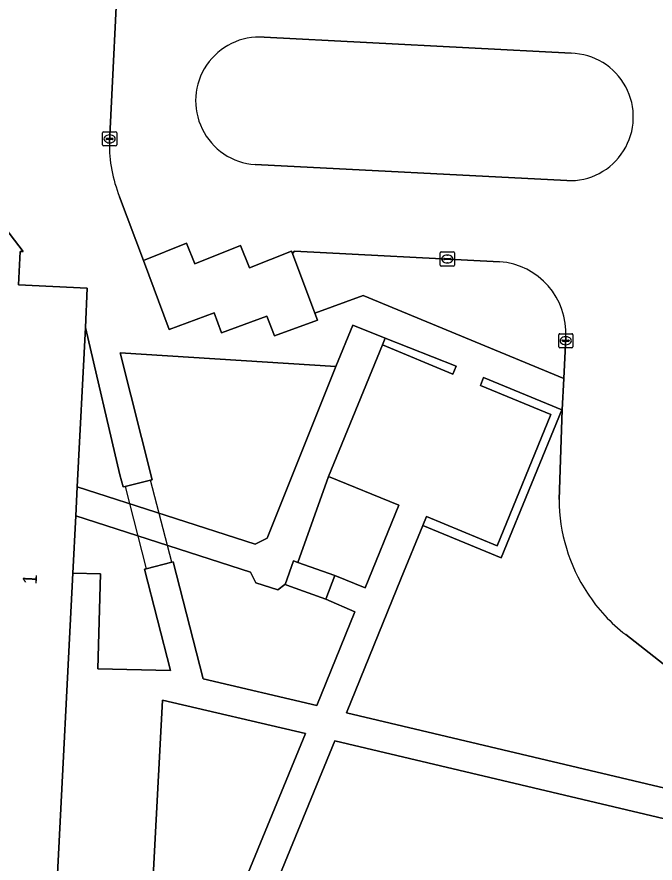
# Model space of a CAD drawing. Extents: x 161758 to 162722, y 384793 to 385405.
# Drawn here: x 161993.6 to 162038.8, y 385039.1 to 385099.1 of the extents above; entities that cross this region are included whole.
import ezdxf

# ---------------------------------------------------------------- set-up
doc = ezdxf.new("R2010")
doc.units = 0
for name, color, linetype in [('IMGEO_Berm_halfverhard', 7, 'Continuous'), ('IMGEO_Dek', 7, 'Continuous'), ('IMGEO_Erf', 7, 'Continuous'), ('IMGEO_Groenvoorziening', 7, 'Continuous'), ('IMGEO_Haag', 7, 'Continuous'), ('IMGEO_Kolk', 7, 'Continuous'), ('IMGEO_Muur', 7, 'Continuous'), ('IMGEO_Pand', 7, 'Continuous'), ('IMGEO_Pand_nummerreeks', 7, 'Continuous'), ('IMGEO_Parkeervlak_open', 7, 'Continuous'), ('IMGEO_Voetpad_op_trap', 7, 'Continuous'), ('IMGEO_Voetpad_open', 7, 'Continuous')]:
    doc.layers.add(name, color=color, linetype=linetype)

msp = doc.modelspace()

# ---------------------------------------------------------------- linework, layer by layer
at = {"layer": 'IMGEO_Berm_halfverhard'}
for points in [[(162032.226, 385071.255), (162032.207, 385071.263), (162027.911, 385060.765), (162022.337, 385063.052), (162020.819, 385059.326), (162016.934, 385049.788), (162056.758, 385040.344), (162056.822, 385040.582)], [(162031.999, 385064.905), (162032.226, 385071.255)], [(162051.708, 385043.574), (162043.338, 385050.139), (162036.73, 385055.322)]]:
    msp.add_lwpolyline(points, dxfattribs=at)
for centre, radius, start, end in [((162044.225, 385064.98), 12.226, 180.35037, 213.32333), ((162044.204, 385064.966), 12.201, 213.32477, 232.22495)]:
    msp.add_arc(centre, radius, start, end, dxfattribs=at)
at = {"layer": 'IMGEO_Dek'}
msp.add_lwpolyline([(162003.052, 385066.268), (162001.253, 385065.825), (162002.75, 385059.996), (162004.555, 385060.459)], close=True, dxfattribs=at)
at = {"layer": 'IMGEO_Erf'}
msp.add_lwpolyline([(162047.619, 384999.899), (162047.744, 385003.397), (162053.158, 385003.197), (162053.585, 385012.029), (162066.381, 385011.411), (162066.398, 385011.78), (162066.718, 385011.765), (162066.15, 385000), (162066.13, 384999.593), (162065.805, 384999.613), (162065.836, 384999.999), (162064.378, 385000.072), (162064.076, 384993.966), (162065.114, 384993.915), (162065.359, 384998.935), (162066.644, 384998.872), (162068.359, 385036.234), (162065.731, 385036.372), (162065.348, 385036.139), (162016.114, 385047.802), (162008.112, 385028.282), (162006.105, 385028.38), (162006.004, 385026.3)], dxfattribs=at)
at = {"layer": 'IMGEO_Groenvoorziening'}
for points in [[(162032.854, 385096.526), (162011.098, 385097.667)], [(162010.46, 385088.638), (162032.562, 385087.501)], [(162027.785, 385081.756), (162013.261, 385082.503), (162013.107, 385082.336), (162014.691, 385078.105), (162018.111, 385079.365), (162032.337, 385073.48), (162032.489, 385076.387)]]:
    msp.add_lwpolyline(points, dxfattribs=at)
for points in [[(162016.186, 385074.325), (162000.899, 385075.296), (162003.17, 385066.297), (162003.052, 385066.268), (162001.253, 385065.825), (162001.117, 385065.791), (162000.884, 385066.653), (161998.431, 385077.099), (161997.857, 385065.807), (162010.464, 385061.741), (162011.315, 385062.167)], [(162019.48, 385075.851), (162024.467, 385073.792), (162024.712, 385074.352), (162019.681, 385076.343)], [(162032.207, 385071.263), (162026.642, 385073.54), (162026.425, 385072.985), (162031.418, 385070.919), (162027.614, 385061.623), (162022.598, 385063.692), (162022.337, 385063.052), (162027.911, 385060.765)], [(162020.639, 385064.489), (162015.666, 385066.538), (162013.488, 385060.442), (162016.117, 385059.508), (162018.254, 385058.633)], [(162012.968, 385058.742), (162012.587, 385058.876), (162012.567, 385058.883), (162012.071, 385058.505), (162010.512, 385059.001), (162010.134, 385059.757), (161997.752, 385063.747), (161997.545, 385059.678), (161999.514, 385059.621), (161999.318, 385052.903), (162004.455, 385052.781), (162002.613, 385059.961), (162002.75, 385059.996), (162004.555, 385060.459), (162004.664, 385060.487), (162006.78, 385052.198), (162014.831, 385050.292), (162017.539, 385056.941), (162015.471, 385057.824)], [(162014.038, 385048.308), (162003.897, 385050.684), (162003.171, 385036.866), (162005.966, 385036.715), (162005.697, 385031.996), (162007.278, 385031.894)]]:
    msp.add_lwpolyline(points, close=True, dxfattribs=at)
for centre, radius, start, end in [((162010.773, 385093.153), 4.526, 85.87566, 266.0406), ((162032.752, 385092.012), 4.515, 267.5846, 88.70914), ((162027.401, 385076.675), 5.096, 356.76216, 85.68369)]:
    msp.add_arc(centre, radius, start, end, dxfattribs=at)
at = {"layer": 'IMGEO_Haag'}
msp.add_lwpolyline([(162019.48, 385075.851), (162024.467, 385073.792), (162024.712, 385074.352), (162019.681, 385076.343)], close=True, dxfattribs=at)
at = {"layer": 'IMGEO_Kolk'}
for p, q in [((161999.726, 385090.96), (162000.578, 385090.96)), ((161999.651, 385090.034), (161999.651, 385090.886)), ((161999.91, 385090.454), (161999.91, 385090.466)), ((162000.348, 385090.417), (161999.95, 385090.417)), ((161999.953, 385090.503), (162000.351, 385090.503)), ((162000.139, 385090.74), (162000.164, 385090.74)), ((162000.394, 385090.466), (162000.394, 385090.454)), ((162000.652, 385090.886), (162000.652, 385090.034)), ((162000.578, 385089.96), (161999.726, 385089.96)), ((162000.162, 385090.18), (162000.137, 385090.18)), ((162023.583, 385081.52), (162023.583, 385082.372)), ((162023.658, 385082.446), (162024.51, 385082.446)), ((162023.842, 385081.94), (162023.842, 385081.952)), ((162023.885, 385081.989), (162024.283, 385081.989)), ((162024.071, 385082.226), (162024.096, 385082.226)), ((162024.326, 385081.952), (162024.326, 385081.94)), ((162024.584, 385082.372), (162024.584, 385081.52)), ((162024.51, 385081.446), (162023.658, 385081.446)), ((162024.28, 385081.903), (162023.882, 385081.903)), ((162024.094, 385081.666), (162024.069, 385081.666)), ((162031.976, 385075.726), (162031.976, 385076.578)), ((162032.051, 385076.652), (162032.903, 385076.652)), ((162032.977, 385076.578), (162032.977, 385075.726)), ((162032.235, 385076.146), (162032.235, 385076.158)), ((162032.673, 385076.109), (162032.275, 385076.109)), ((162032.278, 385076.195), (162032.676, 385076.195)), ((162032.464, 385076.432), (162032.489, 385076.432)), ((162032.719, 385076.158), (162032.719, 385076.146)), ((162032.903, 385075.652), (162032.051, 385075.652)), ((162032.487, 385075.872), (162032.462, 385075.872))]:
    msp.add_line(p, q, dxfattribs=at)
for points in [[(161999.726, 385090.96), (162000.578, 385090.96)], [(161999.651, 385090.034), (161999.651, 385090.886)], [(162000.652, 385090.886), (162000.652, 385090.034)], [(162000.578, 385089.96), (161999.726, 385089.96)], [(162023.583, 385081.52), (162023.583, 385082.372)], [(162023.658, 385082.446), (162024.51, 385082.446)], [(162024.584, 385082.372), (162024.584, 385081.52)], [(162024.51, 385081.446), (162023.658, 385081.446)], [(162031.976, 385075.726), (162031.976, 385076.578)], [(162032.051, 385076.652), (162032.903, 385076.652)], [(162032.977, 385076.578), (162032.977, 385075.726)], [(162032.903, 385075.652), (162032.051, 385075.652)]]:
    msp.add_lwpolyline(points, dxfattribs=at)
for centre, radius, start, end in [((161999.728, 385090.884), 0.0765, 91.55205, 178.44795), ((161999.728, 385090.884), 0.0765, 91.55205, 178.44795), ((162000.576, 385090.884), 0.0765, 1.55205, 88.44795), ((162000.576, 385090.884), 0.0765, 1.55205, 88.44795), ((161999.95, 385090.463), 0.0403, 85.87752, 175.75265), ((161999.947, 385090.453), 0.0366, 178.93798, 274.71019), ((162000.351, 385090.46), 0.043, 264.86636, 352.45326), ((162000.355, 385090.465), 0.0386, 1.73085, 96.63898), ((161999.728, 385090.036), 0.0765, 181.55205, 268.44795), ((161999.728, 385090.036), 0.0765, 181.55205, 268.44795), ((162000.576, 385090.036), 0.0765, 271.55205, 358.44795), ((162000.576, 385090.036), 0.0765, 271.55205, 358.44795), ((162023.66, 385082.37), 0.0765, 91.55205, 178.44795), ((162023.66, 385082.37), 0.0765, 91.55205, 178.44795), ((162023.882, 385081.949), 0.0403, 85.87752, 175.75265), ((162024.287, 385081.951), 0.0386, 1.73085, 96.63898), ((162024.508, 385082.37), 0.0765, 1.55205, 88.44795), ((162024.508, 385082.37), 0.0765, 1.55205, 88.44795), ((162023.66, 385081.522), 0.0765, 181.55205, 268.44795), ((162023.66, 385081.522), 0.0765, 181.55205, 268.44795), ((162023.879, 385081.939), 0.0366, 178.93798, 274.71019), ((162024.283, 385081.946), 0.043, 264.86636, 352.45326), ((162024.508, 385081.522), 0.0765, 271.55205, 358.44795), ((162024.508, 385081.522), 0.0765, 271.55205, 358.44795), ((162032.053, 385076.576), 0.0765, 91.55205, 178.44795), ((162032.053, 385076.576), 0.0765, 91.55205, 178.44795), ((162032.901, 385076.576), 0.0765, 1.55205, 88.44795), ((162032.901, 385076.576), 0.0765, 1.55205, 88.44795), ((162032.275, 385076.155), 0.0403, 85.87752, 175.75265), ((162032.272, 385076.145), 0.0366, 178.93798, 274.71019), ((162032.676, 385076.152), 0.043, 264.86636, 352.45326), ((162032.68, 385076.157), 0.0386, 1.73085, 96.63898), ((162032.053, 385075.728), 0.0765, 181.55205, 268.44795), ((162032.053, 385075.728), 0.0765, 181.55205, 268.44795), ((162032.901, 385075.728), 0.0765, 271.55205, 358.44795), ((162032.901, 385075.728), 0.0765, 271.55205, 358.44795)]:
    msp.add_arc(centre, radius, start, end, dxfattribs=at)
for centre, major_axis, ratio, start_param, end_param in [((162000.138, 385090.46), (-0.387, 0.002), 0.722429, 4.712389, 7.853982), ((162000.163, 385090.46), (-0.39, 0.002), 0.717154, 1.570796, 4.712389), ((162024.07, 385081.946), (-0.387, 0.002), 0.722429, 4.712389, 7.853982), ((162024.095, 385081.946), (-0.39, 0.002), 0.717154, 1.570796, 4.712389), ((162032.463, 385076.152), (-0.387, 0.002), 0.722429, 4.712389, 7.853982), ((162032.488, 385076.152), (-0.39, 0.002), 0.717154, 1.570796, 4.712389)]:
    msp.add_ellipse(centre, major_axis=major_axis, ratio=ratio, start_param=start_param, end_param=end_param, dxfattribs=at)
at = {"layer": 'IMGEO_Muur'}
for points in [[(162017.381, 385077.253), (162016.186, 385074.325)], [(162019.48, 385075.851), (162019.681, 385076.343)], [(162015.666, 385066.538), (162019.48, 385075.851)]]:
    msp.add_lwpolyline(points, dxfattribs=at)
at = {"layer": 'IMGEO_Pand'}
msp.add_lwpolyline([(161996.437, 385037.903), (161997.545, 385059.678), (161997.752, 385063.747), (161997.857, 385065.807), (161998.431, 385077.099), (161998.572, 385079.867), (161993.689, 385080.115), (161993.809, 385082.482), (161994.032, 385082.469), (161989.801, 385087.971)], dxfattribs=at)
at = {"layer": 'IMGEO_Parkeervlak_open'}
msp.add_lwpolyline([(162013.107, 385082.336), (162013.044, 385082.505), (162010.073, 385081.309), (162009.43, 385082.905), (162006.195, 385081.602), (162005.606, 385083.065), (162002.545, 385081.833), (162004.366, 385076.946), (162007.558, 385078.122), (162008.086, 385076.707), (162011.301, 385077.9), (162011.826, 385076.504), (162014.885, 385077.615), (162014.691, 385078.105)], close=True, dxfattribs=at)
at = {"layer": 'IMGEO_Voetpad_op_trap'}
msp.add_lwpolyline([(162016.117, 385059.508), (162013.488, 385060.442), (162013.182, 385060.551), (162012.587, 385058.876), (162012.968, 385058.742), (162015.471, 385057.824)], close=True, dxfattribs=at)
at = {"layer": 'IMGEO_Voetpad_open'}
for points in [[(161906.144, 385108.941), (161977.597, 385105.328), (161995.883, 385104.404), (162000.829, 385104.149), (162000.14, 385090.222)], [(162000.14, 385090.222), (162000.829, 385104.149), (161995.883, 385104.404), (161977.597, 385105.328), (161977.45, 385102.402), (161977.382, 385100.813), (161979.762, 385100.69), (161979.765, 385100.88), (161985.24, 385093.706), (161985.821, 385092.944), (161990.125, 385096.301), (161990.031, 385094.355), (161989.72, 385094.124), (161989.886, 385093.899)], [(162011.098, 385097.667), (162032.854, 385096.526)], [(162032.562, 385087.501), (162010.46, 385088.638)], [(161989.801, 385087.971), (161994.032, 385082.469), (161993.809, 385082.482), (161993.689, 385080.115), (161998.572, 385079.867), (161998.431, 385077.099), (162000.884, 385066.653), (162001.117, 385065.791), (162001.253, 385065.825), (162003.052, 385066.268), (162003.17, 385066.297), (162000.899, 385075.296), (162016.186, 385074.325), (162017.381, 385077.253), (162019.681, 385076.343), (162024.712, 385074.352), (162024.467, 385073.792), (162019.48, 385075.851), (162015.666, 385066.538), (162020.639, 385064.489), (162018.254, 385058.633), (162016.117, 385059.508), (162015.471, 385057.824), (162017.539, 385056.941), (162014.831, 385050.292), (162006.78, 385052.198), (162004.664, 385060.487), (162004.555, 385060.459), (162002.75, 385059.996), (162002.613, 385059.961), (162004.455, 385052.781), (161999.318, 385052.903), (161999.514, 385059.621), (161997.545, 385059.678), (161996.437, 385037.903)], [(162007.558, 385078.122), (162004.366, 385076.946), (162002.545, 385081.833), (162000.858, 385086.359)], [(162000.858, 385086.359), (162002.545, 385081.833), (162005.606, 385083.065), (162006.195, 385081.602), (162009.43, 385082.905), (162010.073, 385081.309), (162013.044, 385082.505), (162013.107, 385082.336), (162013.261, 385082.503), (162027.785, 385081.756)], [(162056.758, 385040.344), (162016.934, 385049.788), (162020.819, 385059.326), (162022.337, 385063.052), (162022.598, 385063.692), (162027.614, 385061.623), (162031.418, 385070.919), (162026.425, 385072.985), (162026.642, 385073.54), (162032.207, 385071.263), (162032.226, 385071.255), (162032.337, 385073.48), (162018.111, 385079.365), (162014.691, 385078.105), (162014.885, 385077.615), (162011.826, 385076.504), (162011.301, 385077.9), (162008.086, 385076.707), (162007.558, 385078.122)], [(162032.489, 385076.387), (162032.337, 385073.48), (162032.226, 385071.255), (162031.999, 385064.905)], [(162036.73, 385055.322), (162043.338, 385050.139), (162051.708, 385043.574)], [(162008.112, 385028.282), (162016.114, 385047.802), (162065.348, 385036.139)]]:
    msp.add_lwpolyline(points, dxfattribs=at)
for points in [[(162019.48, 385075.851), (162019.681, 385076.343), (162017.381, 385077.253), (162016.186, 385074.325), (162011.315, 385062.167), (162010.464, 385061.741), (161997.857, 385065.807), (161997.752, 385063.747), (162010.134, 385059.757), (162010.512, 385059.001), (162012.071, 385058.505), (162012.567, 385058.883), (162012.587, 385058.876), (162013.182, 385060.551), (162013.488, 385060.442), (162015.666, 385066.538)], [(162003.052, 385066.268), (162001.253, 385065.825), (162002.75, 385059.996), (162004.555, 385060.459)], [(162014.038, 385048.308), (162007.278, 385031.894), (162005.697, 385031.996), (162005.966, 385036.715), (162003.171, 385036.866), (162003.897, 385050.684)]]:
    msp.add_lwpolyline(points, close=True, dxfattribs=at)
for centre, radius, start, end in [((162010.773, 385093.153), 4.526, 85.87566, 266.0406), ((162032.752, 385092.012), 4.515, 267.5846, 88.70914), ((162009.87, 385090.032), 9.732, 178.88311, 202.17525), ((162009.87, 385090.032), 9.732, 178.88311, 202.17525), ((162027.401, 385076.675), 5.096, 356.76216, 85.68369), ((162044.225, 385064.98), 12.226, 180.35037, 213.32333), ((162044.204, 385064.966), 12.201, 213.32477, 232.22495)]:
    msp.add_arc(centre, radius, start, end, dxfattribs=at)

# ---------------------------------------------------------------- texts
at = {"layer": 'IMGEO_Pand_nummerreeks'}
msp.add_text('1', height=1, rotation=87.08958, dxfattribs=at).set_placement((161994.979, 385058.852))

doc.saveas('drawing.dxf')
